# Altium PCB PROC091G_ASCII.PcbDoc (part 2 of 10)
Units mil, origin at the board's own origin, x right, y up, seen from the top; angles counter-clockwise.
Board outline 4538.11 x 994.94 mil, 8 copper layers (Top Layer, GND1, Sig1, PWR1, PWR2, Sig2, GND2, Bottom Layer), stack 59.155 mil thick; 447 components, 329 nets, 5050 pads, 868 vias.
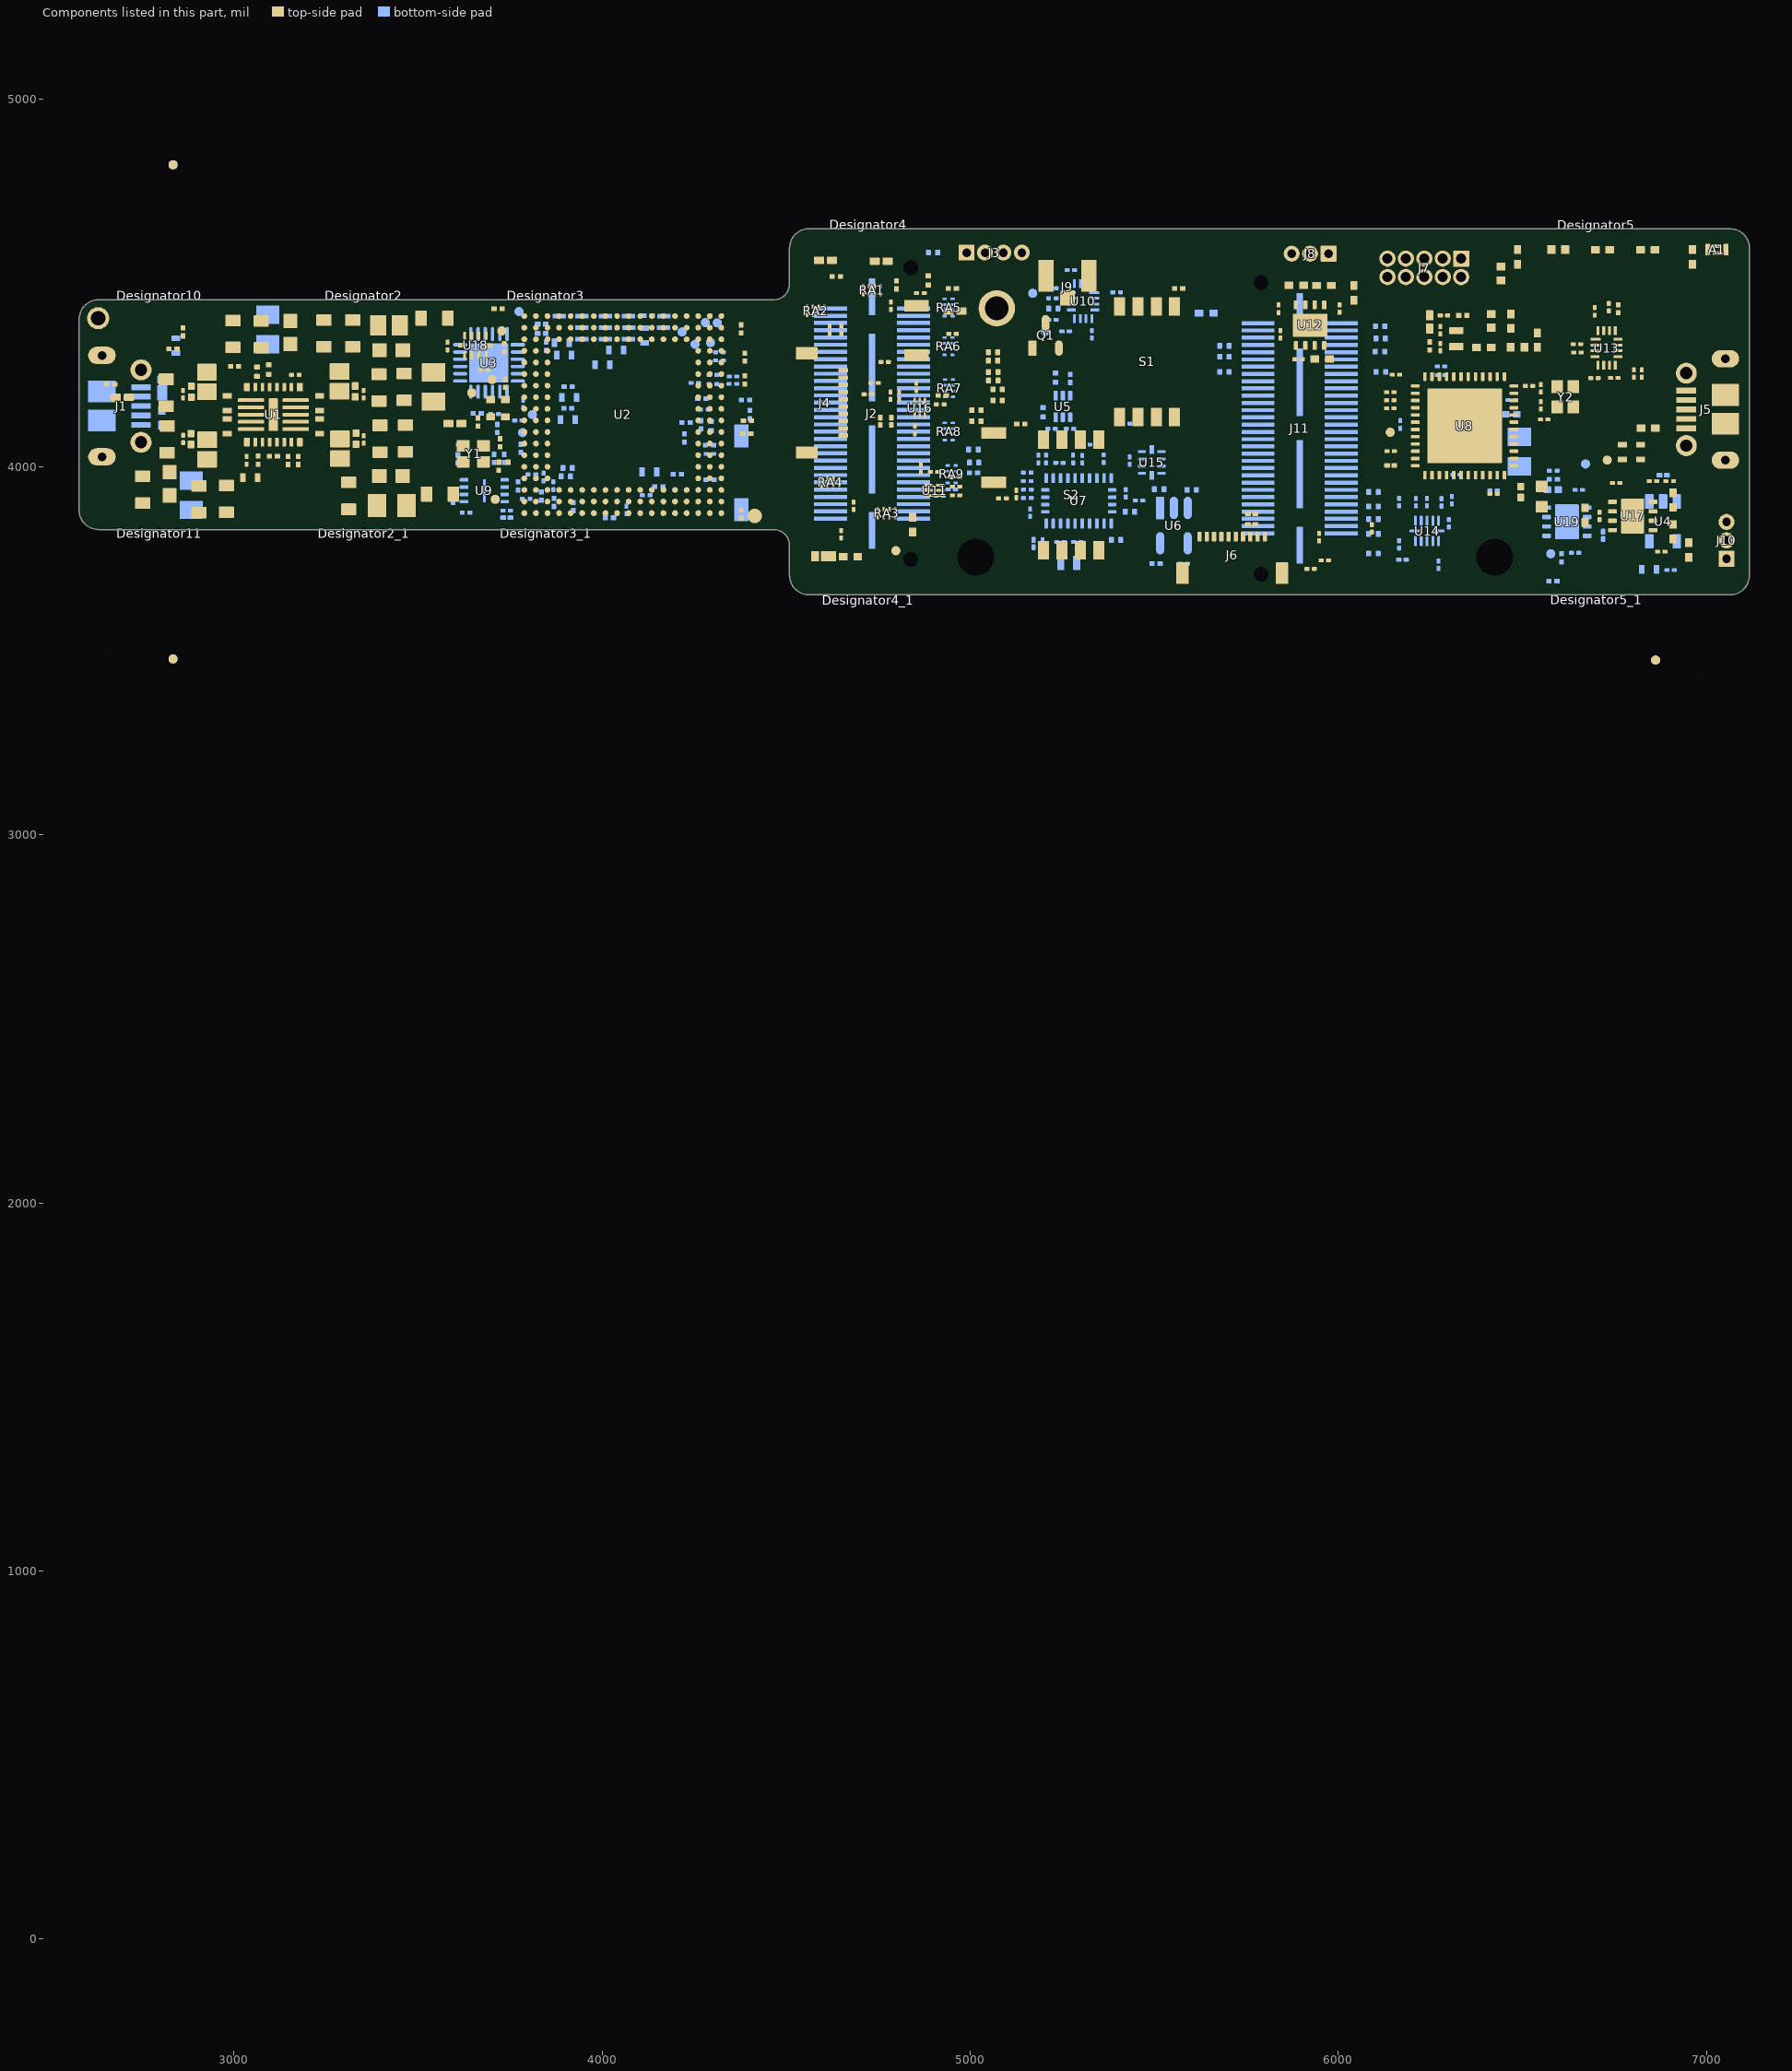
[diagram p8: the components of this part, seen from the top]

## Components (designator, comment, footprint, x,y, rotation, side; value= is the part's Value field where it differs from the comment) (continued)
FID2_1_1_1 "Fiducial" FIDUCIAL6.4-20#2 6862.03,3474.65 r180 top (schematic designator FID2)
FID5_1 "Fiducial" FIDUCIAL6.4-20#2 2834.58,4820.46 r180 bottom (schematic designator FID5)
FID5_1_1 "Fiducial" FIDUCIAL6.4-20#2 2834.58,3477.85 r180 top (schematic designator FID5)
FID5_1_1_1 "Fiducial" FIDUCIAL6.4-20#2 6862.03,3474.65 r0 bottom (schematic designator FID5)
FL2 "BLM15PD300SZ1D" 0402L 2803.8,4133.28 r90 bottom
FL3 "BLM15PD300SZ1D" 0402L 6670.79,3868.56 r90 top
FL4 "BLM15PD300SZ1D" 0402L 5641.61,4417.35 r180 bottom
FL11 "BLM15PD300SZ1D" 0402L 4674.94,3755.5 r180 top locked
FL12 "BLM15PD300SZ1D" 0402L 5955.92,4292.41 r0 top
FL14 "BLM15PD300SZ1D" 0402L 6841.81,4105.18 r180 top
FL22 "BLM15PD300SZ1D" 0402L 4843.47,3842.73 r270 top locked
J1 "105017-0001" CONN_105017-0001 2694.51,4164.78 r90 bottom
J2 "QSH-030-01-L-D-A" Samtec_QSH-030-01-X-D-A 4733.36,4144.5 r0 bottom locked
J3 "M50-3930442" FP-M50-3930442_HDR4-RECOMMENDED_LAND_PATTERN 5065.29,4621.12 r0 bottom
J4 "51441-1093" FP-51441-1093_CONN_SMD_FFC-0 4585.45,4173.34 r270 top locked
J5 "105017-0001" CONN_105017-0001 6998.66,4155.73 r90 top
J6 "51441-1093" FP-51441-1093_CONN_SMD_FFC-0 5711.91,3740.17 r0 top
J7 "GRPB052MWCN-RC" FP-GRPB052MWCN-RC_HDR10-MFG 6233.84,4610.83 r180 top
J8 "M50-3930342" FP-M50-3930342_HDR3-MFG 5923.44,4618.25 r180 top
J9 "U.FL-R-SMT-1(01)" CONN_UFL-R-SMT-1 5264.12,4518.36 r90 top
J10 "M50-3930342" FP-M50-3930342_HDR3-MFG 7094.18,3800 r90 top
J11 "QSH-030-01-L-D-A" Samtec_QSH-030-01-X-D-A 5895.12,4104.5 r180 bottom
L1 "LQG15HS2N4S02D" IND_LQG15H 6487.22,4324.41 r0 top
L2 "MCKK2012TR47M" "FP-MCKK2012TR47M_0805 (2012 Metric)-IPC_C" 2926.51,4230.34 r270 top
L3 "MCKK2012TR47M" "FP-MCKK2012TR47M_0805 (2012 Metric)-IPC_C" 2927.23,4046.77 r90 top
L4 "MCKK2012TR47M" "FP-MCKK2012TR47M_0805 (2012 Metric)-IPC_C" 3286.89,4231.94 r270 top
L5 "MCKK2012TR47M" "FP-MCKK2012TR47M_0805 (2012 Metric)-IPC_C" 3288.17,4048.9 r90 top
L6 "LQG15HS2N4S02D" IND_LQG15H 6415.18,4396.46 r90 top
L7 "MLZ2012N6R8LT000" 0805_HV 6491.96,4040.83 r90 bottom
L8 "BLM18HE152SN1D" 0603L 6552.57,3919.1 r90 top
L9 "LQG15HS2N0S02D" IND_LQG15H 6441.85,4524.72 r90 top
L10 "LQG15HS2N0S02D" IND_LQG15H 6597.79,4589.83 r0 top
L11 "BLM18KG121TH1D" 0603 3426.56,3974.36 r0 top
L12 "BLM18KG121TH1D" 0603 3153.17,4364.72 r90 top
L13 "BLM18KG121TH1D" 0603 2825,3953.79 r270 top
L14 "BLM18KG121TH1D" 0603 3427.09,4316.3 r0 top
L15 "BLM21PG221SN1D" 0805L 3421.44,4384.34 r0 top
LD1 "APHHS1005CGCK" APHHS1005_Green 2696.65,4188.5 r0 top
LD2 "APHHS1005CGCK" APHHS1005_Green 4607.12,4561.07 r180 top locked
LD3 "APHHS1005CGCK" APHHS1005_Green 4758.14,4558.15 r0 top
LD4 "APHHS1005CGCK" APHHS1005_Green 3600,4117.07 r0 top
LD5 "APHHS1005CGCK" APHHS1005_Green 4958.55,4422.56 r0 top
LD6 "APHHS1005CGCK" APHHS1005_Green 6248.18,4393.36 r90 top
Q1 "BSS123-7-F" FP-BSS123-7-F_SOT23-IPC_C 5205.08,4356.86 r90 top
R1 "RR0306P-103-D" FP-RR0306P-103-D_0201-IPC_C#1 5444.85,4116.98 r180 bottom
R2 "RC0201JR-070RL" "FP-RC0201JR-070RL_0201 (0603 Metric)-MFG" 4295.7,4110.3 r270 bottom
R3 "RR0306P-103-D" FP-RR0306P-103-D_0201-IPC_C#1 3793.63,3912.76 r180 bottom
R4 "CRCW0201100KFKED" 0201L 3717.54,4429.01 r180 top
R5 "CRCW0201100KFKED" 0201L 4378.13,4374.27 r270 top
R6 "CRCW020133R2FNED" 0201L 3706.27,4022.49 r270 bottom
R7 "RR0306P-103-D" FP-RR0306P-103-D_0201-IPC_C#1 3840.93,3972.06 r270 bottom
R8 "RR0306P-103-D" FP-RR0306P-103-D_0201-IPC_C#1 3867.48,3948.46 r270 bottom
R9 "CRCW0201100KFKED" 0201L 3835,3920.2 r270 bottom
R10 "AC0201FR-0720RL" FP-AC0201FR-0720RL_0201-IPC_C 4917.01,3921 r180 bottom
R11 "AC0201FR-0720RL" FP-AC0201FR-0720RL_0201-IPC_C 4950.01,3937.94 r180 bottom
R12 "RC0201JR-070RL" "FP-RC0201JR-070RL_0201 (0603 Metric)-MFG" 4898.97,4582.07 r0 bottom
R13 "RC0201JR-07220RL" 0201L 4636.42,4516.76 r180 top locked
R14 "RC0201JR-070RL" "FP-RC0201JR-070RL_0201 (0603 Metric)-MFG" 4886,4506.26 r90 top
R15 "RC0201JR-07220RL" 0201L 3663,4121.49 r90 top
R16 "RC0201FR-077K87L" 0201L 5566.39,4484.46 r180 top
R17 "RC0201JR-07220RL" 0201L 6248.18,4328.17 r90 top
R18 "RR0306P-103-D" FP-RR0306P-103-D_0201-IPC_C#1 5362.78,4021.8 r270 bottom
R19 "RR0306P-103-D" FP-RR0306P-103-D_0201-IPC_C#1 3579.99,4328.04 r90 top
R20 "RR0306P-103-D" FP-RR0306P-103-D_0201-IPC_C#1 6584.18,3988.94 r180 bottom
R21 "RR0306P-103-D" FP-RR0306P-103-D_0201-IPC_C#1 4318.97,4310.76 r0 bottom
R22 "RR0306P-103-D" FP-RR0306P-103-D_0201-IPC_C#1 4318.97,4288.76 r0 bottom
R23 "RR0306P-103-D" FP-RR0306P-103-D_0201-IPC_C#1 4301.24,4249.29 r0 bottom
R24 "CRCW0402200RFKEDHP" FP-CRCW0402200RFKEDHP_0402-IPC_C 6583.18,3937.46 r180 bottom
R25 "RC0201FR-074K99L" 0201L 3065.02,4017.98 r270 top
R26 "RC0201FR-074K99L" 0201L 3146.72,4016.87 r270 top
R27 "RC0201JR-07510RL" 0201L 6606.39,3752.54 r90 bottom
R28 "RC0201JR-070RL" "FP-RC0201JR-070RL_0201 (0603 Metric)-MFG" 3062.78,4258.34 r270 top
R29 "CRCW0201100KFKED" 0201L 6584.18,3965.94 r180 bottom
R30 "RC0201JR-070RL" "FP-RC0201JR-070RL_0201 (0603 Metric)-MFG" 5226,4430 r0 bottom
R31 "RC0201JR-070RL" "FP-RC0201JR-070RL_0201 (0603 Metric)-MFG" 5010.88,4011.31 r0 bottom
R32 "RC0201JR-070RL" "FP-RC0201JR-070RL_0201 (0603 Metric)-MFG" 3094.52,4264.13 r270 top
R33 "RC0201FR-074K99L" 0201L 3175.06,4016.87 r270 top
R34 "RC0201FR-074K99L" 0201L 3001.77,4272.69 r180 top
R35 "RR0306P-103-D" FP-RR0306P-103-D_0201-IPC_C#1 3034.52,4017.52 r270 top
R36 "RR0306P-103-D" FP-RR0306P-103-D_0201-IPC_C#1 3166.73,4249.57 r0 top
R37 "CRCW0201100KFKED" 0201L 5009.23,3983.33 r180 bottom
R38 "RC0201FR-074K99L" 0201L 5272,4240 r90 bottom
R39 "RC0201JR-07510RL" 0201L 2665.67,4224.06 r0 top
R40 "RC0201FR-074K99L" 0201L 3660.79,4145.37 r0 bottom
R41 "RC0201JR-070RL" "FP-RC0201JR-070RL_0201 (0603 Metric)-MFG" 3825.31,4374.62 r90 bottom
R42 "RC0201JR-07220RL" 0201L 4799.25,4494.23 r270 top locked
R43 "RR0306P-103-D" FP-RR0306P-103-D_0201-IPC_C#1 3630.7,3875.43 r0 bottom
R44 "RR0306P-103-D" FP-RR0306P-103-D_0201-IPC_C#1 3619.37,4059.85 r0 bottom
R45 "RR0306P-103-D" FP-RR0306P-103-D_0201-IPC_C#1 3809.22,3978.91 r0 bottom
R46 "CRCW020133R2FNED" 0201L 3595.37,3913.81 r90 bottom
R47 "CRCW020133R2FNED" 0201L 3734.37,4022.49 r270 bottom
R48 "CRCW020133R2FNED" 0201L 3608.37,4021.09 r270 bottom
R49 "CRCW020133R2FNED" 0201L 3771.3,3947.76 r270 bottom
R50 "RC0201JR-071KL" 0201L 2834.18,4320.16 r180 top
R51 "RC0201JR-070RL" "FP-RC0201JR-070RL_0201 (0603 Metric)-MFG" 5232,4241.8 r270 bottom
R52 "RC0201FR-071K96L" 0201L 2861.97,4366.38 r270 top
R53 "RC0402FR-073R83L" "FP-RC0402FR-073R83L_0402 (1005 Metric)-IPC_C" 2884.16,4203.5 r270 top
R54 "RC0402FR-073R83L" "FP-RC0402FR-073R83L_0402 (1005 Metric)-IPC_C" 2883.09,4075.35 r90 top
R55 "RC0402FR-073R83L" "FP-RC0402FR-073R83L_0402 (1005 Metric)-IPC_C" 3329.41,4204.49 r270 top
R56 "RC0402FR-073R83L" "FP-RC0402FR-073R83L_0402 (1005 Metric)-IPC_C" 3331.14,4076.1 r90 top
R57 "RC0201JR-070RL" "FP-RC0201JR-070RL_0201 (0603 Metric)-MFG" 5198,4147.8 r270 bottom
R58 "RC0201JR-070RL" "FP-RC0201JR-070RL_0201 (0603 Metric)-MFG" 5008.99,4046.94 r180 bottom
R59 "RR0306P-103-D" FP-RR0306P-103-D_0201-IPC_C#1 4301.24,4224.76 r0 bottom
R60 "RC0201JR-070RL" "FP-RC0201JR-070RL_0201 (0603 Metric)-MFG" 3846.82,4374.62 r90 bottom
R61 "RC0201JR-070RL" "FP-RC0201JR-070RL_0201 (0603 Metric)-MFG" 3906.47,3996.54 r180 bottom
R62 "RC0201JR-070RL" "FP-RC0201JR-070RL_0201 (0603 Metric)-MFG" 3901.53,3973.85 r180 bottom
R64 "RC0201FR-074K99L" 0201L 3715.38,4103.78 r90 bottom
R65 "RR0306P-103-D" FP-RR0306P-103-D_0201-IPC_C#1 3708.05,4143.04 r0 bottom
R66 "RC0201JR-070RL" "FP-RC0201JR-070RL_0201 (0603 Metric)-IPC_C" 4952.38,4360.97 r0 top
R67 "RC0201JR-070RL" "FP-RC0201JR-070RL_0201 (0603 Metric)-MFG" 5513.34,3938.91 r0 bottom
R68 "RC0201JR-070RL" "FP-RC0201JR-070RL_0201 (0603 Metric)-MFG" 5601.88,3937.06 r180 bottom
R69 "RC0201FR-074K99L" 0201L 5505.11,3737.11 r180 bottom
R70 "RC0201JR-070RL" "FP-RC0201JR-070RL_0201 (0603 Metric)-MFG" 5434,3877.69 r0 bottom
R71 "RC0201JR-070RL" "FP-RC0201JR-070RL_0201 (0603 Metric)-MFG" 5396.26,3801.26 r0 bottom
R72 "RC0201JR-070RL" "FP-RC0201JR-070RL_0201 (0603 METRIC)-IPC_C" 5422.76,3927.24 r270 bottom
R73 "RC0201JR-070RL" "FP-RC0201JR-070RL_0201 (0603 METRIC)-IPC_C" 5458.86,3908 r180 bottom
R74 "RC0201JR-070RL" "FP-RC0201JR-070RL_0201 (0603 METRIC)-IPC_C" 4961.7,3922.44 r180 top
R75 "RC0201JR-071KL" 0201L 3869.6,3903.22 r270 bottom
R76 "RC0201JR-070RL" "FP-RC0201JR-070RL_0201 (0603 METRIC)-IPC_C" 6210.78,3903.45 r90 bottom
R77 "RR0306P-103-D" FP-RR0306P-103-D_0201-IPC_C#1 5185.3,4021 r270 bottom
R78 "RR0306P-103-D" FP-RR0306P-103-D_0201-IPC_C#1 5155,3984 r0 bottom
R79 "ERJ-1GNF4701C" FP-ERJ-1GNF4701C_0201-IPC_C 6300.48,3846.46 r90 bottom
R80 "RR0306P-103-D" FP-RR0306P-103-D_0201-IPC_C#1 5155.48,3915 r0 bottom
R81 "RR0306P-103-D" FP-RR0306P-103-D_0201-IPC_C#1 5315.24,4059.87 r180 bottom
R82 "RR0306P-103-D" FP-RR0306P-103-D_0201-IPC_C#2 5279.72,4021 r270 bottom
R83 "RR0306P-103-D" FP-RR0306P-103-D_0201-IPC_C#1 4277.8,4155.3 r180 bottom
R84 "RR0306P-103-D" FP-RR0306P-103-D_0201-IPC_C#1 4119.89,3922.4 r0 bottom
R85 "RR0306P-103-D" FP-RR0306P-103-D_0201-IPC_C#1 4355.44,4224.99 r0 bottom
R86 "RC0201JR-070RL" "FP-RC0201JR-070RL_0201 (0603 METRIC)-IPC_C" 6141.03,4180.57 r0 top
R87 "RC0201JR-070RL" "FP-RC0201JR-070RL_0201 (0603 METRIC)-IPC_C" 6141.18,4202.46 r0 top
R88 "AC0201FR-0720RL" FP-AC0201FR-0720RL_0201-IPC_C 4807.4,4192.67 r270 top
R89 "CRCW0201100KFKED" 0201L 6338.19,4411.08 r0 top
R90 "RC0201JR-070RL" "FP-RC0201JR-070RL_0201 (0603 METRIC)-IPC_C" 6278.99,4249 r0 bottom
R91 "RC0201JR-070RL" "FP-RC0201JR-070RL_0201 (0603 METRIC)-IPC_C" 6421.95,3926.46 r180 top
R92 "CRCW0201100KFKED" 0201L 6583.22,3689.74 r0 bottom
R93 "RR0306P-103-D" FP-RR0306P-103-D_0201-IPC_C#1 5206.3,4021 r90 bottom
R94 "RR0306P-103-D" FP-RR0306P-103-D_0201-IPC_C#1 5398,4473.91 r0 bottom locked
R95 "RR0306P-103-D" FP-RR0306P-103-D_0201-IPC_C#1 5223.49,4457.6 r180 bottom
R96 "RR0306P-103-D" FP-RR0306P-103-D_0201-IPC_C#1 5155.48,3938 r180 bottom
R97 "RC0201JR-070RL" "FP-RC0201JR-070RL_0201 (0603 METRIC)-IPC_C" 5304.72,4020.49 r90 bottom
R98 "RR0306P-103-D" FP-RR0306P-103-D_0201-IPC_C#1 5155,3961 r180 bottom
R99 "RC0201JR-070RL" "FP-RC0201JR-070RL_0201 (0603 METRIC)-IPC_C" 5223.3,4485 r180 bottom
R100 "RC0201JR-070RL" "FP-RC0201JR-070RL_0201 (0603 METRIC)-IPC_C" 5331,4360.01 r90 bottom
R101 "RC0201JR-070RL" "FP-RC0201JR-070RL_0201 (0603 METRIC)-IPC_C" 5273.16,4534.36 r180 bottom
R102 "RC0201JR-070RL" "FP-RC0201JR-070RL_0201 (0603 METRIC)-IPC_C" 6278.99,4272.45 r0 bottom
R103 "RC0201JR-070RL" "FP-RC0201JR-070RL_0201 (0603 METRIC)-IPC_C" 4355.64,4245.1 r0 bottom
R104 "RR0306P-103-D" FP-RR0306P-103-D_0201-IPC_C#1 4961.33,3971.36 r0 top
R105 "RC0201JR-070RL" "FP-RC0201JR-070RL_0201 (0603 METRIC)-IPC_C" 4865.78,3995.57 r90 top
R106 "RC0201JR-070RL" "FP-RC0201JR-070RL_0201 (0603 METRIC)-IPC_C" 4902.35,3985.56 r0 top locked
R107 "RC0201JR-07510RL" 0201L 4951.64,4484.7 r180 top
R108 "RC0201JR-07510RL" 0201L 4924,4194 r0 top
R109 "RC0201JR-070RL" "FP-RC0201JR-070RL_0201 (0603 Metric)-MFG" 3732.14,4012.38 r0 top
R110 "RR0306P-103-D" FP-RR0306P-103-D_0201-IPC_C#1 6168.27,4114.75 r270 bottom
R111 "RC0201JR-07220RL" 0201L 5137.39,4116.46 r0 top
R112 "RC0201JR-070RL" "FP-RC0201JR-070RL_0201 (0603 METRIC)-IPC_C" 5259.36,4367.46 r0 bottom
R113 "RC0201JR-070RL" "FP-RC0201JR-070RL_0201 (0603 METRIC)-IPC_C" 5223.3,4399 r0 bottom
R114 "CRCW040261R9FKED" 0402L 6909.57,3909.29 r270 top
R115 "RC0201JR-070RL" "FP-RC0201JR-070RL_0201 (0603 Metric)-IPC_C" 6854.79,3961 r0 top
R116 "RC0201JR-070RL" "FP-RC0201JR-070RL_0201 (0603 Metric)-IPC_C" 6754.79,3956 r0 top
R117 "CRCW040261R9FKED" 0402L 6909.66,3823.52 r270 top
R118 "RR0306P-103-D" FP-RR0306P-103-D_0201-IPC_C#1 6696.81,4422 r90 top
R119 "CRCW040261R9FKED" 0402L 5885.96,4492.77 r0 top
R120 "RC0201JR-070RL" "FP-RC0201JR-070RL_0201 (0603 Metric)-IPC_C" 6802.81,4252.99 r90 top
R121 "RC0201JR-070RL" "FP-RC0201JR-070RL_0201 (0603 METRIC)-IPC_C" 6649.04,4333.23 r180 top
R122 "RR0306P-103-D" FP-RR0306P-103-D_0201-IPC_C#1 5837.64,4429.06 r270 top
R123 "RC0201JR-070RL" "FP-RC0201JR-070RL_0201 (0603 METRIC)-IPC_C" 5843.14,4359.71 r90 top
R124 "RR0306P-103-D" FP-RR0306P-103-D_0201-IPC_C#1 4864.68,4471.7 r0 top
R125 "RR0306P-103-D" FP-RR0306P-103-D_0201-IPC_C#1 5087.65,3914.04 r0 top
R126 "CRCW040261R9FKED" 0402L 5960.92,4492.48 r0 top
R127 "RC0201JR-070RL" "FP-RC0201JR-070RL_0201 (0603 METRIC)-IPC_C" 6649.8,4310 r0 top
R128 "RC0201JR-070RL" "FP-RC0201JR-070RL_0201 (0603 METRIC)-IPC_C" 6695.72,4240.71 r180 top
R129 "RC0201JR-070RL" "FP-RC0201JR-070RL_0201 (0603 METRIC)-IPC_C" 5125.2,3925.93 r90 top
R130 "AC0201FR-0720RL" FP-AC0201FR-0720RL_0201-IPC_C 4617.95,4372.15 r270 top locked
R131 "RC0201JR-070RL" "FP-RC0201JR-070RL_0201 (0603 METRIC)-IPC_C" 6321.17,3978.41 r180 bottom
R132 "AC0201FR-0720RL" FP-AC0201FR-0720RL_0201-IPC_C 4783.74,4192.67 r270 top
R133 "AC0201FR-0720RL" FP-AC0201FR-0720RL_0201-IPC_C 4740.67,4227.63 r180 top locked
R134 "RR0306P-103-D" FP-RR0306P-103-D_0201-IPC_C#1 6900.3,3961 r0 top
R135 "AC0201FR-0720RL" FP-AC0201FR-0720RL_0201-IPC_C 4722.06,4196.8 r180 top locked
R136 "RC0201JR-070RL" "FP-RC0201JR-070RL_0201 (0603 Metric)-IPC_C" 6749.82,4241 r0 top
R137 "AC0201FR-0720RL" FP-AC0201FR-0720RL_0201-IPC_C 4649.26,3816.82 r90 top
R138 "AC0201FR-0720RL" FP-AC0201FR-0720RL_0201-IPC_C 4767.38,4284.46 r180 top
R139 "RC0201JR-070RL" "FP-RC0201JR-070RL_0201 (0603 Metric)-IPC_C" 6824.81,4252.99 r270 top
R140 "AC0201FR-0720RL" FP-AC0201FR-0720RL_0201-IPC_C 4683.56,3893.44 r90 top
R141 "RC0201FR-074K99L" 0201L 6760.03,4429.26 r90 top
R142 "RC0201JR-070RL" "FP-RC0201JR-070RL_0201 (0603 Metric)-MFG" 5017.08,4123.69 r0 top
R143 "RC0201JR-070RL" "FP-RC0201JR-070RL_0201 (0603 Metric)-MFG" 5017.08,4153.69 r0 top
R144 "RC0201JR-070RL" "FP-RC0201JR-070RL_0201 (0603 Metric)-MFG" 5074.94,4180.12 r0 top
R145 "RC0201JR-070RL" "FP-RC0201JR-070RL_0201 (0603 Metric)-MFG" 5074.94,4210.12 r0 top
R146 "RC0201JR-070RL" "FP-RC0201JR-070RL_0201 (0603 Metric)-MFG" 5062.8,4234.19 r0 top
R147 "RC0201JR-070RL" "FP-RC0201JR-070RL_0201 (0603 Metric)-MFG" 5062.8,4257.19 r0 top
R148 "RC0201JR-070RL" "FP-RC0201JR-070RL_0201 (0603 Metric)-MFG" 5062.1,4288.03 r0 top
R149 "RC0201JR-070RL" "FP-RC0201JR-070RL_0201 (0603 Metric)-MFG" 5062.1,4311.03 r0 top
R150 "RC0201JR-070RL" "FP-RC0201JR-070RL_0201 (0603 Metric)-MFG" 6113.61,4381.76 r0 bottom
R151 "RC0201JR-070RL" "FP-RC0201JR-070RL_0201 (0603 Metric)-MFG" 6115.41,4348.48 r0 bottom
R152 "RC0201JR-070RL" "FP-RC0201JR-070RL_0201 (0603 Metric)-MFG" 5690.93,4328.4 r0 bottom
R153 "RC0201JR-070RL" "FP-RC0201JR-070RL_0201 (0603 Metric)-MFG" 6113.32,4312.59 r0 bottom
R154 "RC0201JR-070RL" "FP-RC0201JR-070RL_0201 (0603 Metric)-MFG" 5690.93,4298.93 r0 bottom
R155 "RC0201JR-070RL" "FP-RC0201JR-070RL_0201 (0603 Metric)-MFG" 6115.55,4257.57 r0 bottom
R157 "RC0201JR-070RL" "FP-RC0201JR-070RL_0201 (0603 Metric)-MFG" 5690.93,4257.72 r0 bottom
R158 "RC0201FR-0782K5L" 0201L 4228.2,4119.6 r0 bottom
R159 "RC0201JR-07750RL" 0201L 4223.5,4078.1 r270 bottom
R160 "RC0201JR-070RL" "FP-RC0201JR-070RL_0201 (0603 METRIC)-IPC_C" 6280.34,3903.27 r90 bottom
R161 "RC0201JR-070RL" "FP-RC0201JR-070RL_0201 (0603 METRIC)-IPC_C" 6141.18,4158.46 r0 top
R166 "RC0201JR-070RL" "FP-RC0201JR-070RL_0201 (0603 METRIC)-IPC_C" 6240.62,3903.59 r90 bottom
R168 "RC0201JR-070RL" "FP-RC0201JR-070RL_0201 (0603 METRIC)-IPC_C" 6165.24,3903.57 r90 bottom
R170 "RC0201FR-0782K5L" 0201L 4154.35,3946.46 r180 bottom
R171 "RC0201JR-07750RL" 0201L 4204.44,3980.18 r0 bottom
R172 "RC0201FR-0782K5L" 0201L 4401.11,4142.03 r90 bottom
R174 "RC0201FR-077K87L" 0201L 4269.1,4113.8 r90 bottom
R176 "RC0201FR-077K87L" 0201L 4389.6,4181.8 r0 bottom
R177 "RR0306P-103-D" FP-RR0306P-103-D_0201-IPC_C#1 4849.59,4099.95 r90 top
R178 "RR0306P-103-D" FP-RR0306P-103-D_0201-IPC_C#1 4918.69,4169.46 r180 top
R180 "ERJ-1GNF4701C" FP-ERJ-1GNF4701C_0201-IPC_C 6165.19,3789.15 r270 bottom
R181 "ERJ-1GNF4701C" FP-ERJ-1GNF4701C_0201-IPC_C 6091.28,3832.56 r90 top
R182 "RC0201JR-070RL" "FP-RC0201JR-070RL_0201 (0603 METRIC)-IPC_C" 4650.14,4371.83 r270 top locked
R183 "RC0201JR-070RL" "FP-RC0201JR-070RL_0201 (0603 METRIC)-IPC_C" 5947.68,3808.42 r270 top
R184 "RC0201JR-070RL" "FP-RC0201JR-070RL_0201 (0603 METRIC)-IPC_C" 5963.36,3745.98 r0 top
R185 "RC0201JR-070RL" "FP-RC0201JR-070RL_0201 (0603 METRIC)-IPC_C" 5925.33,3722.49 r180 top
R186 "RC0201JR-070RL" "FP-RC0201JR-070RL_0201 (0603 Metric)-MFG" 6095.54,3931.22 r0 bottom
R187 "RC0201JR-070RL" "FP-RC0201JR-070RL_0201 (0603 Metric)-MFG" 6095.54,3892.26 r0 bottom
R188 "RC0201JR-070RL" "FP-RC0201JR-070RL_0201 (0603 Metric)-MFG" 6095.54,3857.41 r0 bottom
R189 "RC0201JR-070RL" "FP-RC0201JR-070RL_0201 (0603 Metric)-MFG" 6095.54,3817.56 r0 bottom
R190 "RC0201JR-070RL" "FP-RC0201JR-070RL_0201 (0603 Metric)-MFG" 6095.54,3764.53 r0 bottom
RA1 "EXB-18VR000X" FP-EXB-18VR000X_0502-MFG 4733.17,4479.49 r180 top locked
RA2 "EXB-18VR000X" FP-EXB-18VR000X_0502-MFG 4580.6,4423.99 r180 top locked
RA3 "EXB-18VR000X" FP-EXB-18VR000X_0502-MFG 4772.94,3873.84 r0 top locked
RA4 "EXB-18VR000X" FP-EXB-18VR000X_0502-MFG 4620.57,3957.49 r0 top locked
RA5 "EXB-18VR000X" FP-EXB-18VR000X_0502-MFG 4941.51,4432.71 r90 bottom locked
RA6 "EXB-18VR000X" FP-EXB-18VR000X_0502-MFG 4941.09,4327.39 r90 bottom locked
RA7 "EXB-18VR000X" FP-EXB-18VR000X_0502-MFG 4942.52,4213.65 r90 bottom locked
RA8 "EXB-18VR000X" FP-EXB-18VR000X_0502-MFG 4941.86,4095.87 r90 bottom locked
RA9 "EXB-18VR000X" FP-EXB-18VR000X_0502-MFG 4949.85,3979.76 r90 bottom locked
S1 "218-4LPST" SW_218-4LPST 5480.37,4285.46 r90 top
S2 "218-4LPST" SW_218-4LPST 5274.37,3923.46 r90 top locked
S3 "CHS-01TA" FP-CHS-01TA_SMT_SW_5MM4_2MM5-MFG 4378.13,3983.7 r270 bottom
SW2 "B3U-1000P" SW_B3U-1000P 4854.16,4369.94 r270 top
SW3 "B3U-1000P" SW_B3U-1000P 5063.87,4024.39 r90 top
TP2 "TESTPOINT" TP_25MIL-SMT 3810.59,4141.77 r90 bottom
TP3 "TESTPOINT" TP_25MIL-SMT 3784,4092.76 r90 bottom
TP4 "TESTPOINT" TP_25MIL-SMT 6671.71,4007.65 r180 bottom
TP5 "TESTPOINT" TP_25MIL-SMT 3709.73,3911.44 r90 top
TP6 "TESTPOINT" TP_25MIL-SMT 4313,4390.94 r0 bottom
TP7 "TESTPOINT" TP_25MIL-SMT 4280.69,4391.59 r270 bottom
TP8 "TESTPOINT" TP_25MIL-SMT 4252.7,4332.6 r90 bottom
TP9 "TESTPOINT" TP_25MIL-SMT 4217.3,4366.19 r90 bottom
TP10 "TESTPOINT" TP_25MIL-SMT 6577.18,3763.46 r270 bottom
TP11 "TP_SM_1MM" TP_SM_1MM 4414.85,3866.34 r90 top
TP12 "TESTPOINT" TP_VIA_060RND040 2631.09,4403.54 r90 top
TP13 "TESTPOINT" TP_25MIL-SMT 4798.18,3771.83 r270 top
TP14 "TESTPOINT" TP_25MIL-SMT 4294.6,4337.1 r180 bottom
TP15 "TESTPOINT" TP_25MIL-SMT 6730.81,4018 r90 top
TP16 "TESTPOINT" TP_25MIL-SMT 6141.18,4093.46 r180 top
TP17 "TESTPOINT" TP_25MIL-SMT 3701,4237 r270 top
TP18 "TESTPOINT" TP_25MIL-SMT 3727.56,4369.01 r90 top
TP19 "TESTPOINT" TP_25MIL-SMT 3645.95,4200.94 r90 top
TP20 "4953" FP-4953_HDR1-MFG 5072.16,4430.47 r180 bottom locked
TP26 "TESTPOINT" TP_25MIL-SMT 3774.42,4421.63 r0 bottom
TP27 "TESTPOINT" TP_25MIL-SMT 5204,4368 r270 bottom
TP46 "TESTPOINT" TP_25MIL-SMT 5169.8,4471.3 r180 bottom
U1 "LP87524JRNFRQ1" RNF0026C 3107,4141.61 r270 top
U2 "XI6843ARQGALP" ALP0180A 4056.48,4141.61 r90 top
U3 "CP2105-F01-GMR" FP-CP2105-F01-GMR_QFN24-EP-IPC_A 3692.64,4282.2 r180 bottom
U4 "TPS79330DBVR" DBV0005A_N 6882.18,3851.63 r270 bottom
U5 "TMP112AQDRLRQ1" DRL0006A 5251.98,4163.77 r270 bottom locked
U6 "CAT24C08TDI-GT3" FP-CAT24C08TDI-GT3_TSOT-23-5-IPC_A 5553.54,3840.01 r270 bottom
U7 "BNO085" FP-BNO085_LGA28-MFG 5294.88,3907.22 r270 bottom
U8 "CC2642R1FRGZR" RGZ0048A 6343.38,4111.11 r270 top
U9 "MX25R1635FZUIH0" USON-8L 3680.29,3934.68 r0 bottom
U10 "TCA6408ARSVR" RSV0016A 5306.8,4449.73 r180 bottom
U11 "SN74LVC1G3157DSFR" DSF0006A 4902.7,3935.72 r0 top locked
U12 "TCAN1042HGVDRBRQ1" DRB0008F 5923.44,4384.46 r90 top
U13 "TS3A5018RSVR" RSV0016A 6728.94,4322.76 r0 top
U14 "TXB0104QRUTRQ1" RUT0012A 6241.04,3825.36 r90 bottom
U15 "TS5A23157RSER" RSE0010A 5493.28,4011.53 r180 bottom
U16 "SN74LVC1G11DSFR" DSF0006A-MFG 4863.37,4159.46 r90 top
U17 "TCAN1042HGVDRBRQ1" DRB0008F 6799.78,3866 r0 top
U18 "TS5A23157RSER" RSE0010A 3655.79,4329.59 r270 top
U19 "TPS2115ADRBR" DRB0008B 6621.18,3850.46 r0 bottom
Y1 "CX2016DB40000D0FLJCC" FP-CX2016DB40000D0FLJCC_SMT_2MM0_1MM6-MFG 3650.54,4035.03 r0 top
Y2 "CX2016DB48000C0WPLA2" FP-CX2016DB48000C0WPLA2_SMD4-MFG 6616.71,4189.85 r270 top
Y3 "ABS05W-32.768KHZ-D-2-T" FP-ABS05W-32.768KHZ-D-2-T_XTAL_SMT_1MM6_1MM0-MFG 6320.71,4347.93 r270 top
Y4 "ABS05W-32.768KHZ-D-2-T" FP-ABS05W-32.768KHZ-D-2-T_XTAL_SMT_1MM6_1MM0-MFG 5267.82,3738.88 r0 bottom
ZZ1 "This Assembly Note is for PCB labels only" AssemblyNoteLabel 2349.62,2814.36 r0 top
ZZ2 "These assemblies are ESD sensitive, ESD precautions shall be observed." AssemblyNote 2346.49,2738.89 r0 top
ZZ3 "These assemblies must be clean and free from flux and all contaminants. Use of no clean flux is not acceptable." AssemblyNote 2346.43,2653.5 r0 top
ZZ4 "These assemblies must comply with workmanship standards IPC-A-610 Class 2, unless otherwise specified." AssemblyNote 2343.34,2567.2 r0 top
ZZ5.1 "Cut the thermal pad(Part Number#GPVOUS-0.125-AC-0816) for the shape and size of the inner surface of the heatsink(Part Number#MCH054) and paste it on the inner surface of the heatsink;" AssemblyNote 2340.76,2492.7 r0 top
ZZ5.2 "Bring the heatsink onto the PCB bottom side (Opposite side of AOP device). Match the teeth in the heatsink with break-away area in the PCB and press the heatsink onto the PCB slightly so as thermal pad is spread all over the area" AssemblyNote 2343.41,2409 r0 top

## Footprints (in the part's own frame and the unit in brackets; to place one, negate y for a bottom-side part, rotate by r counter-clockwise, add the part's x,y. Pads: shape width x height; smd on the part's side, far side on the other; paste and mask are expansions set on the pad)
0201_033L [mm] "0201"
  rect 0.36x0.32 smd mask+0: 1(-0.28,0) 2(0.28,0)
0201L [mm] "Data from Kemet datasheet CC101_COM dated 7/28/11"
  rect 0.36x0.32 smd mask+0: 1(-0.28,0) 2(0.28,0)
0402_070 [mil] "SMD, 2-Leads, Body 1.2x0.7mm, Height 0.7mm"
  rect 15x24 smd: 1(-20,0) 2(20,0)
0402L [mm] "0402 from SM-752 data"
  rect 0.6x0.5 smd: 1(-0.5,0) 2(0.5,0)
0603 [mm] "0603 from SM-752 data"
  rect 1x0.95 smd: 1(-0.8,0) 2(0.8,0)
  silkscreen extent -1.52,-0.69 1.52,0.69
0603L [mm] "0603 from SM-752 data"
  rect 0.8x0.85 smd: 1(-0.7,0) 2(0.7,0)
  silkscreen extent -0.07,-0.33 0.07,0.33
0805_HV [mil] "0805 with 30mil clearance between pads"
  rect 50x63 smd: 1(-40,0) 2(40,0)
  silkscreen extent -74,-40 74,40
0805L [mm] "0805 from SM-752 data"
  rect 1.1x1.4 smd: 1(-0.75,0) 2(0.75,0)
ALP0180A [mm] "BGA-180"
  round 0.4 smd: A1(-6.8,6.8) A2(-6,6.8) A3(-5.2,6.8) A4(-4.4,6.8) A5(-3.6,6.8) A6(-2.8,6.8) A7(-2,6.8) A8(-1.2,6.8) A9(-0.4,6.8) A10(0.4,6.8) A11(1.2,6.8) A12(2,6.8) A13(2.8,6.8) A14(3.6,6.8) A15(4.4,6.8) A16(5.2,6.8) A17(6,6.8) A18(6.8,6.8) B1(-6.8,6) B2(-6,6) B3(-5.2,6) B4(-4.4,6) B5(-3.6,6) B6(-2.8,6) B7(-2,6) B8(-1.2,6) B9(-0.4,6) B10(0.4,6) B11(1.2,6) B12(2,6) B13(2.8,6) B14(3.6,6) B15(4.4,6) B16(5.2,6) B17(6,6) B18(6.8,6) C1(-6.8,5.2) C2(-6,5.2) C3(-5.2,5.2) C4(-4.4,5.2) C5(-3.6,5.2) C6(-2.8,5.2) C7(-2,5.2) C8(-1.2,5.2) C9(-0.4,5.2) C10(0.4,5.2) C11(1.2,5.2) C12(2,5.2) C13(2.8,5.2) C14(3.6,5.2) C15(4.4,5.2) C16(5.2,5.2) C17(6,5.2) C18(6.8,5.2) D1(-6.8,4.4) D2(-6,4.4) D3(-5.2,4.4) D16(5.2,4.4) D17(6,4.4) D18(6.8,4.4) E1(-6.8,3.6) E2(-6,3.6) E3(-5.2,3.6) E16(5.2,3.6) E17(6,3.6) E18(6.8,3.6) F1(-6.8,2.8) F2(-6,2.8) F3(-5.2,2.8) F16(5.2,2.8) F17(6,2.8) F18(6.8,2.8) G1(-6.8,2) G2(-6,2) G3(-5.2,2) G16(5.2,2) G17(6,2) G18(6.8,2) H1(-6.8,1.2) H2(-6,1.2) H3(-5.2,1.2) H16(5.2,1.2) H17(6,1.2) H18(6.8,1.2) J1(-6.8,0.4) J2(-6,0.4) J3(-5.2,0.4) J16(5.2,0.4) J17(6,0.4) J18(6.8,0.4) K1(-6.8,-0.4) K2(-6,-0.4) K3(-5.2,-0.4) K16(5.2,-0.4) K17(6,-0.4) K18(6.8,-0.4) L1(-6.8,-1.2) L2(-6,-1.2) L3(-5.2,-1.2) L16(5.2,-1.2) L17(6,-1.2) L18(6.8,-1.2) M1(-6.8,-2) M2(-6,-2) M3(-5.2,-2) M16(5.2,-2) M17(6,-2) M18(6.8,-2) N1(-6.8,-2.8) N2(-6,-2.8) N3(-5.2,-2.8) N16(5.2,-2.8) N17(6,-2.8) N18(6.8,-2.8) P1(-6.8,-3.6) P2(-6,-3.6) P3(-5.2,-3.6) P16(5.2,-3.6) P17(6,-3.6) P18(6.8,-3.6) R1(-6.8,-4.4) R2(-6,-4.4) R3(-5.2,-4.4) R16(5.2,-4.4) R17(6,-4.4) R18(6.8,-4.4) T1(-6.8,-5.2) T2(-6,-5.2) T3(-5.2,-5.2) T4(-4.4,-5.2) T5(-3.6,-5.2) T6(-2.8,-5.2) T7(-2,-5.2) T8(-1.2,-5.2) T9(-0.4,-5.2) T10(0.4,-5.2) T11(1.2,-5.2) T12(2,-5.2) T13(2.8,-5.2) T14(3.6,-5.2) T15(4.4,-5.2) T16(5.2,-5.2) T17(6,-5.2) T18(6.8,-5.2) U1(-6.8,-6) U2(-6,-6) U3(-5.2,-6) U4(-4.4,-6) U5(-3.6,-6) U6(-2.8,-6) U7(-2,-6) U8(-1.2,-6) U9(-0.4,-6) U10(0.4,-6) U11(1.2,-6) U12(2,-6) U13(2.8,-6) U14(3.6,-6) U15(4.4,-6) U16(5.2,-6) U17(6,-6) U18(6.8,-6) V1(-6.8,-6.8) V2(-6,-6.8) V3(-5.2,-6.8) V4(-4.4,-6.8) V5(-3.6,-6.8) V6(-2.8,-6.8) V7(-2,-6.8) V8(-1.2,-6.8) V9(-0.4,-6.8) V10(0.4,-6.8) V11(1.2,-6.8) V12(2,-6.8) V13(2.8,-6.8) V14(3.6,-6.8) V15(4.4,-6.8) V16(5.2,-6.8) V17(6,-6.8) V18(6.8,-6.8)
  silkscreen extent -7.5,-7.5 7.5,7.5
APHHS1005_Green [mm] "SMD, 2-Leads, Body 1x0.5mm"
  rrect20% 0.7x0.5 smd: 1(-0.45,0) 2(0.45,0)
  silkscreen extent -0.8,-0.65 1.2,0.65
AssemblyNote [mil] "Assembly Note"
AssemblyNoteLabel [mil] "Assembly Note for PCB Labels"
BRAKE_WAY_HOLES1X2 [mil]
  round 27 hole 32 unplated mask+0: ""(-50,30.26) ""(0,30.26) ""(50,30.26)
CONN_105017-0001 [mm] "Molex Micro USB-B"
  rect 0.4x1.35 smd: 1(-1.3,1.35) 2(-0.65,1.35) 3(0,1.35) 4(0.65,1.35) 5(1.3,1.35)
  oval 1.2x1.9 hole 0.6 slot 1.3 at 90 deg: 6(-3.5,-1.35) 9(3.5,-1.35)
  rect 1.5x1.9 smd: 7(-1,-1.35) 8(1,-1.35)
  round 1.45 hole 0.85: 10(2.5,1.35) 11(-2.5,1.35)
  Top Layer region: -3.5,-0.4 -2.3,-0.4 -2.3,-2.3 -3.5,-2.3
  Top Layer region: 3.499,-2.3 2.299,-2.3 2.299,-0.4 3.499,-0.4
  silkscreen extent -4.1,-0.2 4.1,1.4
CONN_UFL-R-SMT-1 [mm] "Hirose recommended land pattern http://www.hirose.co.jp/cataloge_hp/e32119372.pdf 2009.2"
  rect 1.05x1 smd paste-0.1 mask+0: 1(-1.525,0)
  rect 2x0.9 on Top Paste: 2(0,1.5) 3(0,-1.5)
  rect 2x0.9 on Top Solder: 2(0,1.5) 3(0,-1.5)
  rect 2.2x1.05 smd paste-2 mask+0: 2(0,1.475) 3(0,-1.475)
  Top Layer keep-out region: -0.8,-0.703 1.1,-0.703 1.1,0.697 -0.8,0.697
  silkscreen extent -1.7,-1.7 1.7,1.7
DBV0005A_N [mm] "SOT23, 5-Leads, Body 2.9x1.6mm, Pitch 0.95mm, Lead Span 2.8mm, IPC Medium Density"
  rrect17% 1x0.6 smd: 1(-1.375,0.95) 2(-1.375,0) 3(-1.375,-0.95) 4(1.375,-0.95) 5(1.375,0.95)
  silkscreen extent -0.25,-1.55 0.25,1.55
DRB0008B [mm] "SON, 8-Leads, Body 3x3mm, Pitch 0.65mm, Thermal Pad 2.4x1.65mm, TI Recommended"
  rrect33% 0.6x0.3 smd: 1(-1.4,0.975) 2(-1.4,0.325) 3(-1.4,-0.325) 4(-1.4,-0.975) 5(1.4,-0.975) 6(1.4,-0.325) 7(1.4,0.325) 8(1.4,0.975)
  rrect9% 1.47x1.06 on Bottom Paste: 9(0,-0.63) 9(0,0.63)
  rrect6% 1.65x2.4 smd paste-1.2: 9(0,0)
  silkscreen extent -1.73,-1.73 1.73,1.73
DRB0008F [mm] "SON, 8-Leads, Body 3x3mm, Pitch 0.65mm, Thermal Pad 2.4x1.6mm, TI Recommended"
  rrect33% 0.6x0.3 smd: 1(-1.4,0.975) 2(-1.4,0.325) 3(-1.4,-0.325) 4(-1.4,-0.975) 5(1.4,-0.975) 6(1.4,-0.325) 7(1.4,0.325) 8(1.4,0.975)
  rrect9% 1.47x1.07 on Top Paste: 9(0,0.635) 9(0,-0.635)
  rrect6% 1.6x2.4 smd paste-1.2: 9(0,0)
  silkscreen extent -1.73,-1.73 1.73,1.73
DRL0006A [mm] "SOTFL, 6-Flat Leads, Body 1.2x1.6x0.6mm, Pitch 0.5mm, TI recommended"
  rrect33% 0.67x0.3 smd: 1(-0.74,0.5) 2(-0.74,0) 3(-0.74,-0.5) 4(0.74,-0.5) 5(0.74,0) 6(0.74,0.5)
  silkscreen extent -0.9,-0.95 0.5,0.95
DSF0006A [mm] "TI recommended land pattern"
  rrect59% 0.6x0.17 smd mask+0: 1(-0.4,0.35) 2(-0.4,0) 3(-0.4,-0.35) 4(0.4,-0.35) 5(0.4,0) 6(0.4,0.35)
  silkscreen extent -0.6,-0.63 0.6,0.63
DSF0006A-MFG [mm]
  rrect59% 0.6x0.17 smd paste+0 mask+0: 1(-0.4,0.35) 2(-0.4,0) 3(-0.4,-0.35) 4(0.4,-0.35) 5(0.4,0) 6(0.4,0.35)
  silkscreen extent -1.14,-0.85 0.53,1.02
DSN2_0603 [mm] "SMD, 2-Leads, Body 1.6x0.8mm"
  rect 0.52x0.7 smd: 1(-0.64,0)
  rect 1.05x0.7 smd: 2(0.275,0)
  silkscreen extent -1.4,-0.75 0.8,0.65
FIDUCIAL6.4-20#1 [mil]
FIDUCIAL6.4-20#2 [mil]
  round 25 smd mask+0: 1(0,0)
FP-250R05L120JV4T_0201-IPC_C [mm]
  rrect38% 0.363x0.263 smd paste+0 mask+0: 1(-0.25,0) 2(0.25,0)
FP-4953_HDR1-MFG [mm]
  round 2.5 hole 1.65 paste-1000 mask+0: 1(0,0)
FP-51441-1093_CONN_SMD_FFC-0 [mm]
  rrect33% 0.3x0.65 smd paste+0 mask+0: 1(-2.25,1.775) 2(-1.75,1.775) 3(-1.25,1.775) 4(-0.75,1.775) 5(-0.25,1.775) 6(0.25,1.775) 7(0.75,1.775) 8(1.25,1.775) 9(1.75,1.775) 10(2.25,1.775)
  rrect12% 0.85x1.5 smd paste+0 mask+0: 11(-3.425,-0.75) 12(3.425,-0.75)
FP-ABS05W-32.768KHZ-D-2-T_XTAL_SMT_1MM6_1MM0-MFG [mm]
  rrect20% 0.5x1 smd paste+0 mask+0: 1(-0.55,0) 2(0.55,0)
FP-AC0201FR-0720RL_0201-IPC_C [mil]
  rrect38% 13.94x10.34 smd paste+0 mask+0: 1(-10.01,0) 2(10.01,0)
FP-ANT016008LCS2442MA2_SMT_ANT-0 [mm]
  rrect29% 0.35x0.8 smd paste+0 mask+0: 1(-0.625,0) 4(0.625,0)
  rrect38% 0.6x0.26 smd paste+0 mask+0: 2-3(0,-0.235) 5-6(0,0.235)
FP-BNO085_LGA28-MFG [mm]
  rrect40% 0.675x0.25 smd paste+0 mask+0: 1(1.562,2.25) 6(-1.562,2.25) 7(-1.562,1.75) 8(-1.562,1.25) 9(-1.562,0.75) 10(-1.562,0.25) 11(-1.562,-0.25) 12(-1.562,-0.75) 13(-1.562,-1.25) 14(-1.562,-1.75) 15(-1.562,-2.25) 20(1.562,-2.25) 21(1.562,-1.75) 22(1.562,-1.25) 23(1.562,-0.75) 24(1.562,-0.25) 25(1.562,0.25) 26(1.562,0.75) 27(1.562,1.25) 28(1.562,1.75)
  rrect40% 0.25x0.575 smd paste+0 mask+0: 2(0.75,2.312) 3(0.25,2.312) 4(-0.25,2.312) 5(-0.75,2.312) 16(-0.75,-2.312) 17(-0.25,-2.312) 18(0.25,-2.312) 19(0.75,-2.312)
FP-BSS123-7-F_SOT23-IPC_C [mm]
  rrect18% 1.059x0.547 smd paste+0 mask+0: 1(-0.877,0.915)
  rrect100% 1.059x0.547 smd paste+0 mask+0: 2(-0.877,-0.915) 3(0.877,0)
FP-CAT24C08TDI-GT3_TSOT-23-5-IPC_A [mm]
  rrect18% 1.54x0.566 smd paste+0 mask+0: 1(-1.216,0.95)
  rrect100% 1.54x0.566 smd paste+0 mask+0: 2(-1.216,0) 3(-1.216,-0.95) 4(1.216,-0.95) 5(1.216,0.95)
FP-CGA4J1X7T0J226M125AC_0805-MFG [mm]
  rrect13% 0.8x1.05 smd paste+0 mask+0: 1(-0.925,0) 2(0.925,0)
  silkscreen extent -0.15,-0.77 0.15,0.77
FP-CHS-01TA_SMT_SW_5MM4_2MM5-MFG [mm]
  rrect10% 1.6x1 smd paste+0 mask+0: 1(-2.54,0) 2(2.54,0)
FP-CL03A103KA3NNNC_0201-IPC_C [mil]
  rrect38% 13.94x10.34 smd paste+0 mask+0: 1(-10.01,0) 2(10.01,0)
FP-CL03A105MO3NRNH_0201-IPC_C [mil]
  rrect33% 15.83x11.94 smd paste+0 mask+0: 1(-9.87,0) 2(9.87,0)
FP-CL05A226MQ5N6J8_0402-IPC_C [mil]
  rrect21% 20.29x18.6 smd paste+0 mask+0: 1(-14.9,0) 2(14.9,0)
FP-CP2105-F01-GMR_QFN24-EP-IPC_A [mm]
  rrect42% 0.979x0.239 smd paste+0 mask+0: 1(-1.99,1.25)
  rrect100% 0.979x0.239 smd paste+0 mask+0: 2(-1.99,0.75) 3(-1.99,0.25) 4(-1.99,-0.25) 5(-1.99,-0.75) 6(-1.99,-1.25) 13(1.99,-1.25) 14(1.99,-0.75) 15(1.99,-0.25) 16(1.99,0.25) 17(1.99,0.75) 18(1.99,1.25)
  rrect100% 0.239x0.979 smd paste+0 mask+0: 7(-1.25,-1.99) 8(-0.75,-1.99) 9(-0.25,-1.99) 10(0.25,-1.99) 11(0.75,-1.99) 12(1.25,-1.99) 19(1.25,1.99) 20(0.75,1.99) 21(0.25,1.99) 22(-0.25,1.99) 23(-0.75,1.99) 24(-1.25,1.99)
  rrect4% 2.7x2.7 smd paste-1000 mask+0: 25(0,0)
FP-CRCW0402200RFKEDHP_0402-IPC_C [mil]
  rrect21% 20.29x18.6 smd paste+0 mask+0: 1(-14.9,0) 2(14.9,0)
FP-CX2016DB40000D0FLJCC_SMT_2MM0_1MM6-MFG [mm]
  rrect13% 0.9x0.8 smd paste+0 mask+0: 1(-0.7,-0.55) 2(0.7,-0.55) 3(0.7,0.55) 4(-0.7,0.55)
FP-CX2016DB48000C0WPLA2_SMD4-MFG [mm]
  rrect13% 0.9x0.8 smd paste+0 mask+0: 1(-0.7,-0.55) 2(0.7,-0.55) 3(0.7,0.55) 4(-0.7,0.55)
  silkscreen extent -1.85,-1.35 1.05,1.35
FP-ERJ-1GNF4701C_0201-IPC_C [mil]
  rrect38% 13.94x10.34 smd paste+0 mask+0: 1(-10.01,0) 2(10.01,0)
FP-EXB-18VR000X_0502-MFG [mm]
  rrect57% 0.175x0.3 smd paste+0 mask+0: 1(-0.6,-0.275) 2(-0.2,-0.275) 3(0.2,-0.275) 4(0.6,-0.275) 5(0.6,0.275) 6(0.2,0.275) 7(-0.2,0.275) 8(-0.6,0.275)
"FP-GRM033R6YA104KE14D_0201 (0603 Metric)-IPC_C" [mil]
  rrect38% 13.94x10.34 smd paste+0 mask+0: 1(-10.01,0) 2(10.01,0)
"FP-GRM0335C1H8R0BA01D_0201 (0603 metric)-IPC_C" [mil]
  rrect38% 13.94x10.34 smd paste+0 mask+0: 1(-10.01,0) 2(10.01,0)
FP-GRPB052MWCN-RC_HDR10-MFG [mm]
  rrect9% 1.12x1.12 hole 0.7 paste-1000 mask+0: 1(-2.54,1.15)
  round 1.12 hole 0.7 paste-1000 mask+0: 2(-2.54,2.42) 3(-1.27,1.15) 4(-1.27,2.42) 5(0,1.15) 6(0,2.42) 7(1.27,1.15) 8(1.27,2.42) 9(2.54,1.15) 10(2.54,2.42)
  silkscreen extent -3.77,-0.7 3.42,1.17
FP-M50-3930342_HDR3-MFG [mm]
  rrect9% 1.1x1.1 hole 0.6 paste-1000 mask+0: 1(-1.27,1)
  round 1.1 hole 0.6 paste-1000 mask+0: 2(0,1) 3(1.27,1)
  silkscreen extent -2.15,-0.6 2.15,2.09
FP-M50-3930442_HDR4-RECOMMENDED_LAND_PATTERN [mm]
  rrect9% 1.1x1.1 hole 0.6 paste-1000 mask+0: 1(-1.905,1)
  round 1.1 hole 0.6 paste-1000 mask+0: 2(-0.635,1) 3(0.635,1) 4(1.905,1)
"FP-MCKK2012TR47M_0805 (2012 Metric)-IPC_C" [mil]
  rrect9% 45.45x53.39 smd paste+0 mask+0: 1(-26.61,0) 2(26.61,0)
"FP-RC0201JR-070RL_0201 (0603 Metric)-IPC_C" [mil]
  rrect38% 13.94x10.34 smd paste+0 mask+0: 1(-10.01,0) 2(10.01,0)
"FP-RC0201JR-070RL_0201 (0603 METRIC)-IPC_C" [mil]
  rrect38% 13.94x10.34 smd paste+0 mask+0: 1(-10.01,0) 2(10.01,0)
"FP-RC0201JR-070RL_0201 (0603 Metric)-MFG" [mm]
  rrect29% 0.35x0.4 smd paste+0 mask+0: 1(-0.325,0) 2(0.325,0)
"FP-RC0402FR-073R83L_0402 (1005 Metric)-IPC_C" [mil]
  rrect21% 20.29x18.6 smd paste+0 mask+0: 1(-14.9,0) 2(14.9,0)
FP-RR0306P-103-D_0201-IPC_C#1 [mil]
  rrect37% 13.31x10.73 smd paste+0 mask+0: 1(-10.52,0) 2(10.52,0)
FP-RR0306P-103-D_0201-IPC_C#2 [mil]
  rrect38% 13.94x10.34 smd paste+0 mask+0: 1(-10.52,0)
  rrect37% 13.31x10.73 smd paste+0 mask+0: 2(10.52,0)
"FP-TMK063CG391JT-F_0201 (0603 Metric)-IPC_C" [mil]
  rrect38% 13.94x10.34 smd paste+0 mask+0: 1(-10.01,0) 2(10.01,0)
IND_LQG15H [mm] "MuRata"
  rect 0.55x0.6 smd: 1(-0.475,0) 2(0.475,0)
  silkscreen extent -1.3,-0.3 -0.95,0.3
MHNP_2-5 [mil]
  round 95 hole 100 unplated mask+0: ""(0,0)
  Keep-Out Layer circle w1: c0,0 r100
MHNP_M2_PANHEAD_PHILLIPS [mil]
  round 83 hole 88 unplated mask+0: ""(0,0)
  Keep-Out Layer circle w1: c0,0 r88
RGZ0048A [mm] "VQFN-48"
  rrect42% 0.6x0.24 smd: 1(-3.4,2.75) 2(-3.4,2.25) 3(-3.4,1.75) 4(-3.4,1.25) 5(-3.4,0.75) 6(-3.4,0.25) 7(-3.4,-0.25) 8(-3.4,-0.75) 9(-3.4,-1.25) 10(-3.4,-1.75) 11(-3.4,-2.25) 12(-3.4,-2.75) 25(3.4,-2.75) 26(3.4,-2.25) 27(3.4,-1.75) 28(3.4,-1.25) 29(3.4,-0.75) 30(3.4,-0.25) 31(3.4,0.25) 32(3.4,0.75) 33(3.4,1.25) 34(3.4,1.75) 35(3.4,2.25) 36(3.4,2.75)
  rrect42% 0.24x0.6 smd: 13(-2.75,-3.4) 14(-2.25,-3.4) 15(-1.75,-3.4) 16(-1.25,-3.4) 17(-0.75,-3.4) 18(-0.25,-3.4) 19(0.25,-3.4) 20(0.75,-3.4) 21(1.25,-3.4) 22(1.75,-3.4) 23(2.25,-3.4) 24(2.75,-3.4) 37(2.75,3.4) 38(2.25,3.4) 39(1.75,3.4) 40(1.25,3.4) 41(0.75,3.4) 42(0.25,3.4) 43(-0.25,3.4) 44(-0.75,3.4) 45(-1.25,3.4) 46(-1.75,3.4) 47(-2.25,3.4) 48(-2.75,3.4)
  rrect2% 5.15x5.15 smd paste-2.6: 49(0,0)
RNF0026C [mm] "QFN, 26-Leads, Body 4x4.5mm, Pitch 0.5mm"
  rrect25% 0.6x0.4 smd paste-0.3: 1(-1.9,1.825) 8(-1.9,-1.825) 14(1.9,-1.825) 21(1.9,1.825)
  rrect40% 0.6x0.25 smd paste+0: 2(-1.9,1.25) 3(-1.9,0.75) 4(-1.9,0.25) 5(-1.9,-0.25) 6(-1.9,-0.75) 7(-1.9,-1.25) 15(1.9,-1.25) 16(1.9,-0.75) 17(1.9,-0.25) 18(1.9,0.25) 19(1.9,0.75) 20(1.9,1.25)
  rrect40% 0.25x1.82 smd paste-1: 9(-1,-1.54) 10(-0.5,-1.54) 11(0,-1.54) 12(0.5,-1.54) 13(1,-1.54) 22(1,1.54) 23(0.5,1.54) 24(0,1.54) 25(-0.5,1.54) 26(-1,1.54)
  rrect15% 2.24x0.66 smd paste-1: 27(0,0)
  rrect33% 0.6x0.3 on Top Paste: ""(-1.9,1.775) ""(-1.9,-1.775) ""(1.9,1.775) ""(1.9,-1.775)
  rrect33% 0.3x0.825 on Top Paste: ""(-1.575,2.037) ""(-1.575,-2.037) ""(1.575,2.037) ""(1.575,-2.037)
  rrect40% 0.25x0.81 on Top Paste: ""(-1,2.045) ""(-1,1.035) ""(-1,-1.035) ""(-1,-2.045) ""(-0.5,2.045) ""(-0.5,1.035) ""(-0.5,-1.035) ""(-0.5,-2.045) ""(0,2.045) ""(0,1.035) ""(0,-1.035) ""(0,-2.045) ""(0.5,2.045) ""(0.5,1.035) ""(0.5,-1.035) ""(0.5,-2.045) ""(1,2.045) ""(1,1.035) ""(1,-1.035) ""(1,-2.045)
  rrect15% 0.98x0.66 on Top Paste: ""(-0.59,0) ""(0.59,0)
  silkscreen extent -2.45,-2.7 2.45,2.7
RSE0010A [mm] "QFN, 10-Leads, Body 1.5x2mm, Pitch 0.5mm, TI Recommended"
  rect 0.55x0.2 smd: 1(-0.675,0.75) 2(-0.675,0.25) 3(-0.675,-0.25) 4(-0.675,-0.75) 6(0.675,-0.75) 7(0.675,-0.25) 8(0.675,0.25) 9(0.675,0.75)
  rect 0.3x0.6 smd: 5(0,-0.9) 10(0,0.9)
  silkscreen extent -1.07,-1.17 0.77,1.18
RSV0016A [mm] "QFN, 16-Leads, Body 1.8x2.6mm, Pitch 0.4mm, TI Recommended"
  rect 0.7x0.2 smd: 1(-0.75,0.6)
  rect 0.6x0.2 smd: 2(-0.8,0.2) 3(-0.8,-0.2) 4(-0.8,-0.6) 9(0.8,-0.6) 10(0.8,-0.2) 11(0.8,0.2) 12(0.8,0.6)
  rect 0.2x0.6 smd: 5(-0.6,-1.2) 6(-0.2,-1.2) 7(0.2,-1.2) 8(0.6,-1.2) 13(0.6,1.2) 14(0.2,1.2) 15(-0.2,1.2) 16(-0.6,1.2)
  silkscreen extent -1.08,-1.33 1.08,1.45
RUT0012A [mm] "QFN, 12-Leads, Body 1.7x2mm, Pitch 0.4mm, TI Recommended"
  rrect50% 0.7x0.2 smd: 1(-0.7,0.8) 2(-0.7,0.4) 3(-0.7,0) 4(-0.7,-0.4) 5(-0.7,-0.8) 7(0.7,-0.8) 8(0.7,-0.4) 9(0.7,0) 10(0.7,0.4) 11(0.7,0.8)
  rrect50% 0.2x0.7 smd: 6(0,-0.85) 12(0,0.85)
  silkscreen extent -0.9,-1.2 0.9,1.2
Samtec_QSH-030-01-X-D-A [mm] "Receptacle, 0.5 mm, 30x2, TH"
  rect 2.27x0.279 smd: 1(-2.865,7.25) 2(2.865,7.25) 3(-2.865,6.75) 4(2.865,6.75) 5(-2.865,6.25) 6(2.865,6.25) 7(-2.865,5.75) 8(2.865,5.75) 9(-2.865,5.25) 10(2.865,5.25) 11(-2.865,4.75) 12(2.865,4.75) 13(-2.865,4.25) 14(2.865,4.25) 15(-2.865,3.75) 16(2.865,3.75) 17(-2.865,3.25) 18(2.865,3.25) 19(-2.865,2.75) 20(2.865,2.75) 21(-2.865,2.25) 22(2.865,2.25) 23(-2.865,1.75) 24(2.865,1.75) 25(-2.865,1.25) 26(2.865,1.25) 27(-2.865,0.75) 28(2.865,0.75) 29(-2.865,0.25) 30(2.865,0.25) 31(-2.865,-0.25) 32(2.865,-0.25) 33(-2.865,-0.75) 34(2.865,-0.75) 35(-2.865,-1.25) 36(2.865,-1.25) 37(-2.865,-1.75) 38(2.865,-1.75) 39(-2.865,-2.25) 40(2.865,-2.25) 41(-2.865,-2.75) 42(2.865,-2.75) 43(-2.865,-3.25) 44(2.865,-3.25) 45(-2.865,-3.75) 46(2.865,-3.75) 47(-2.865,-4.25) 48(2.865,-4.25) 49(-2.865,-4.75) 50(2.865,-4.75) 51(-2.865,-5.25) 52(2.865,-5.25) 53(-2.865,-5.75) 54(2.865,-5.75) 55(-2.865,-6.25) 56(2.865,-6.25) 57(-2.865,-6.75) 58(2.865,-6.75) 59(-2.865,-7.25) 60(2.865,-7.25)
  round 0 hole 1.02 unplated: MH1(2.67,10.065) MH2(2.67,-10.065)
  rect 0.43x2.54 smd: MP1(0,8.065) MP4(0,-8.065)
  rect 0.43x4.7 smd: MP2(0,3.175) MP3(0,-3.175)
  silkscreen extent -3.9,-10.66 3.62,10.66
SW_218-4LPST [mil] "CTS Components"
  rect 50x30 smd: 1(-150,75) 2(-150,25) 3(-150,-25) 4(-150,-75) 5(150,-75) 6(150,-25) 7(150,25) 8(150,75)
  silkscreen extent -114,-123 114,123
SW_B3U-1000P [mm] "OMRON"
  rect 0.8x1.7 smd: 1(-1.7,0) 2(1.7,0)
  silkscreen extent -1.5,-1.25 1.5,1.25
TP_25MIL-SMT [mil]
  round 25 smd mask+0: 1(0,0)
TP_SM_1MM [mm] "1mm Test Point, SMT"
  round 1 smd paste-0.5: 1(0,0)
TP_VIA_060RND040 [mil] "TP_VIA_060RND040"
  round 60 hole 40: 1(0,0)
USON-8L [mm] "SON, 8-Leads, Body 3x2mm, Pitch 0.5mm"
  rrect40% 0.6x0.25 smd: 1(-1.4,0.75) 2(-1.4,0.25) 3(-1.4,-0.25) 4(-1.4,-0.75) 5(1.4,-0.75) 6(1.4,-0.25) 7(1.4,0.25) 8(1.4,0.75)
  rrect50% 0.2x1.6 smd: 9(0,0)
  silkscreen extent -1.55,-1.17 0.65,1.17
